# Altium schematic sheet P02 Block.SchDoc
size 297 x 209 mm
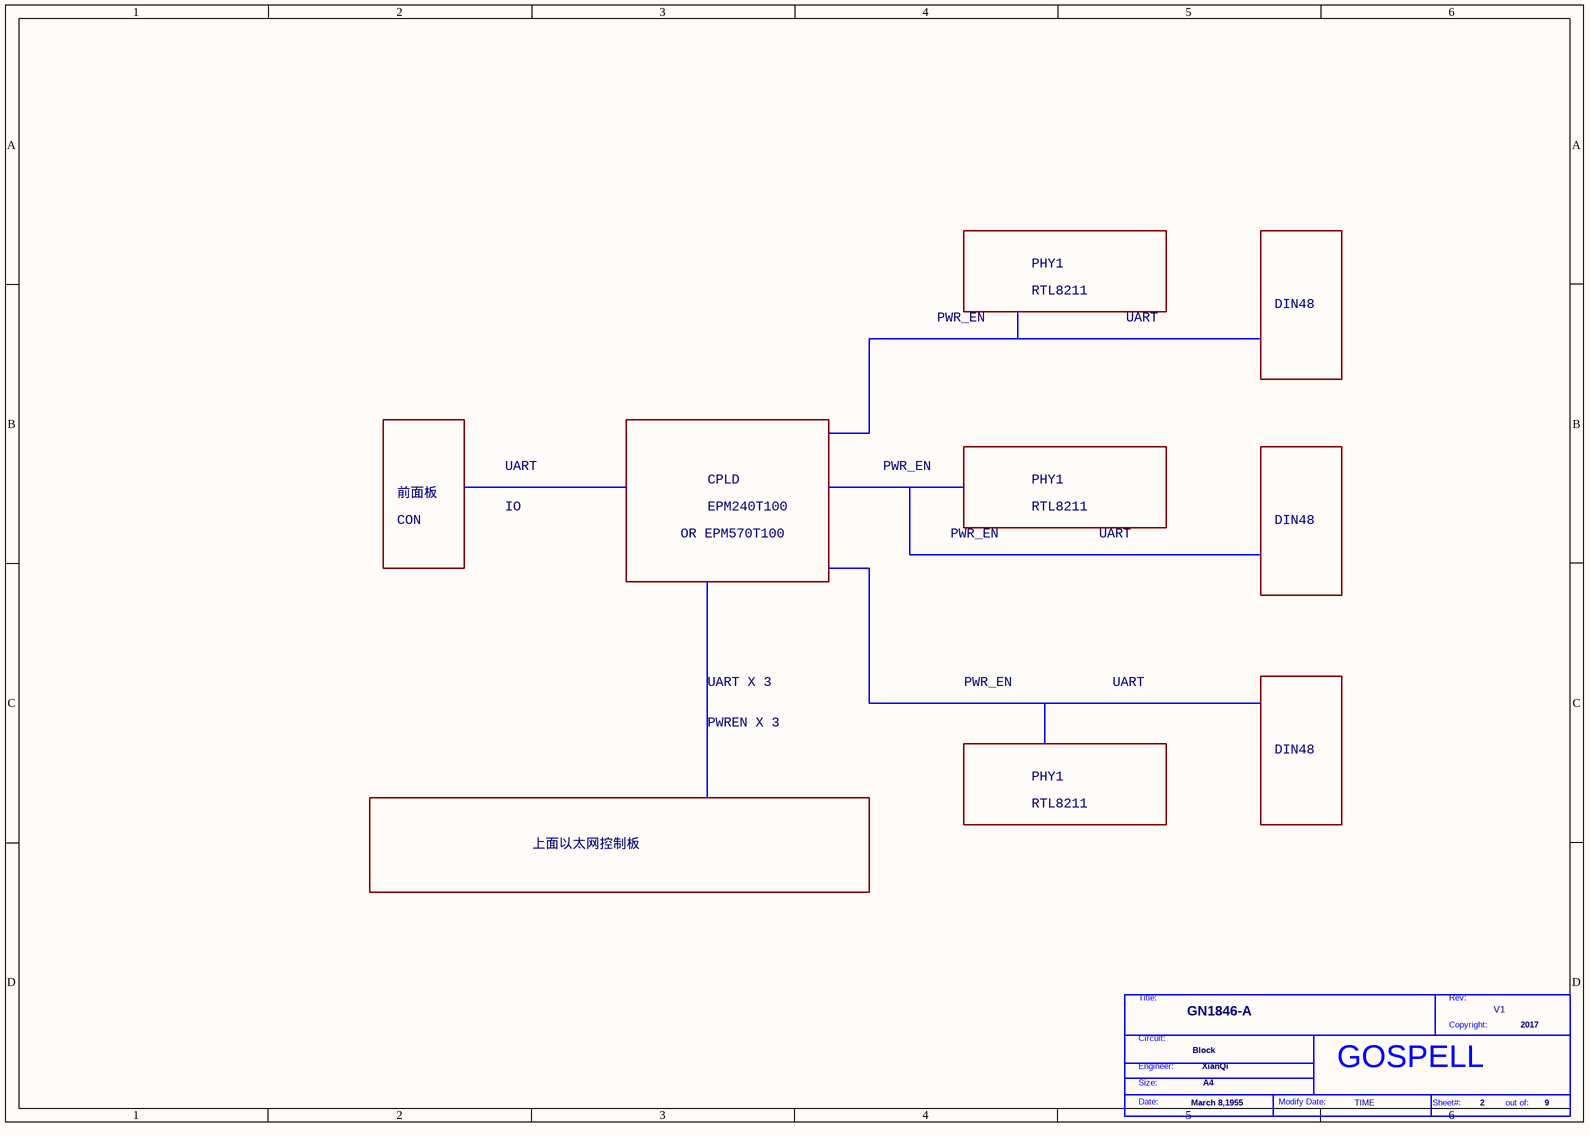
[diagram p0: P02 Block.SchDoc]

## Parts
*  Doc: Block  Page Count: 9  Page Number: 2  Page Create Date: March 8,1955  Page Size: A4  RevCode: V1  Title: GN1846-A  Copyright: 2017  Engineer: XianQi  Page Modify Date: TIME  (hidden comment: GOSPELL)  (graphical)

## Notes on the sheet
- PHY1
- PWR_EN
- RTL8211
- UART
- DIN48
- 前面板
- CON
- IO
- OR EPM570T100
- CPLD
- EPM240T100
- UART X 3
- PWREN X 3
- 上面以太网控制板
